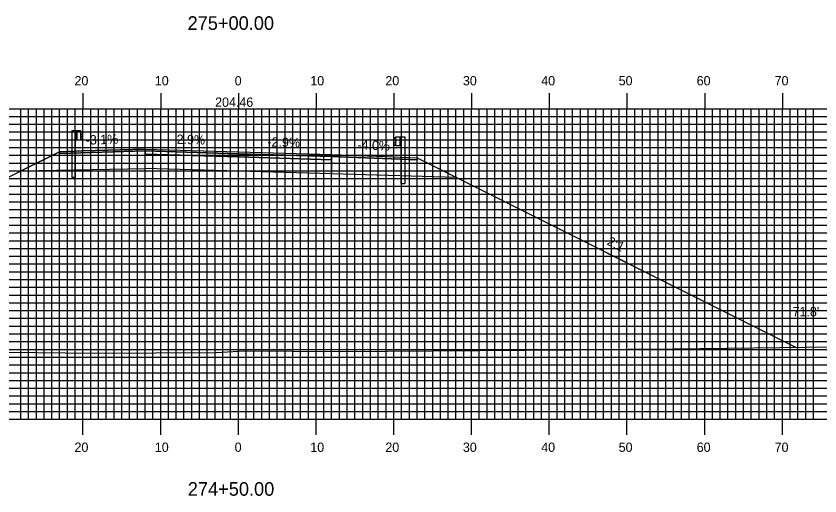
# Model space of a CAD drawing. Extents: x 1809406 to 1809749, y 442591 to 442811.
# Drawn here: x 1809543.2 to 1809646.7, y 442658.8 to 442720.6 of the extents above; entities that cross this region are included whole.
import ezdxf

# ---------------------------------------------------------------- set-up
doc = ezdxf.new("R2010")
doc.units = 0
for name, color, linetype in [('ANNOTATION', 7, 'Continuous'), ('D_Guardrail_Beam_Lt', 7, 'Continuous'), ('D_Guardrail_Beam_Rt', 7, 'Continuous'), ('D_Roadway_Centerline', 7, 'Continuous'), ('D_Roadway_Centerline_Text', 7, 'Continuous'), ('D_Roadway_Edge_Shoulder', 7, 'Continuous'), ('D_Roadway_Edge_TW', 7, 'Continuous'), ('D_Roadway_Pavement', 7, 'Continuous'), ('D_Roadway_SlopeLines', 7, 'Continuous'), ('D_Roadway_SubGrade', 7, 'Continuous'), ('D_Text_Standard', 7, 'Continuous'), ('H_V ANNOTATION', 7, 'Continuous'), ('MAJOR', 7, 'Continuous'), ('MINOR', 7, 'Continuous'), ('S_Roadway_Centerline', 7, 'Continuous')]:
    doc.layers.add(name, color=color, linetype=linetype)

msp = doc.modelspace()

# ---------------------------------------------------------------- linework, layer by layer
at = {"layer": 'D_Guardrail_Beam_Lt'}
for p, q in [((1809550.41, 442705.8), (1809550.41, 442699.8)), ((1809550.88, 442705.8), (1809550.41, 442705.8)), ((1809551.57, 442705.8), (1809550.88, 442705.8)), ((1809550.88, 442705.8), (1809550.88, 442704.64)), ((1809550.94, 442705.8), (1809550.94, 442704.64)), ((1809551.05, 442705.8), (1809551.05, 442704.64)), ((1809551.57, 442704.64), (1809551.57, 442705.8)), ((1809551.57, 442705.72), (1809551.64, 442705.71)), ((1809551.57, 442705.26), (1809551.57, 442705.19)), ((1809551.8, 442705.46), (1809551.6, 442705.32)), ((1809551.66, 442705.7), (1809551.8, 442705.6)), ((1809550.88, 442704.64), (1809551.57, 442704.64)), ((1809550.9, 442699.8), (1809550.9, 442704.64)), ((1809551.64, 442704.74), (1809551.57, 442704.72)), ((1809551.6, 442705.12), (1809551.8, 442704.99)), ((1809551.8, 442704.84), (1809551.66, 442704.74)), ((1809550.9, 442699.8), (1809550.41, 442699.8))]:
    msp.add_line(p, q, dxfattribs=at)
for centre, major_axis, start_param, end_param in [((1809551.65, 442705.26), (-0.0789, 0), 5.323254, 6.283185), ((1809551.65, 442705.19), (-0.0789, 0), 6.283185, 7.243116), ((1809551.63, 442705.67), (0.0417, 0), 0.959931, 1.376053), ((1809551.75, 442705.53), (0.0877, 0), 5.323254, 7.243116), ((1809551.63, 442704.78), (0.0417, 0), 4.907132, 5.323254), ((1809551.75, 442704.91), (0.0877, 0), 5.323254, 7.243116)]:
    msp.add_ellipse(centre, major_axis=major_axis, ratio=0.995501, start_param=start_param, end_param=end_param, dxfattribs=at)
at = {"layer": 'D_Guardrail_Beam_Rt'}
for p, q in [((1809592.02, 442704.93), (1809591.87, 442704.83)), ((1809591.87, 442704.69), (1809592.07, 442704.55)), ((1809592.07, 442704.35), (1809591.87, 442704.22)), ((1809592.11, 442704.95), (1809592.03, 442704.94)), ((1809592.1, 442704.49), (1809592.1, 442704.42)), ((1809592.11, 442705.03), (1809592.8, 442705.03)), ((1809592.11, 442703.87), (1809592.11, 442705.03)), ((1809592.63, 442705.03), (1809592.63, 442703.87)), ((1809592.73, 442705.03), (1809592.73, 442703.87)), ((1809592.8, 442705.03), (1809593.27, 442705.03)), ((1809592.8, 442705.03), (1809592.8, 442703.87)), ((1809593.27, 442705.03), (1809593.27, 442699.03)), ((1809591.87, 442704.07), (1809592.02, 442703.97)), ((1809592.03, 442703.97), (1809592.11, 442703.95)), ((1809592.8, 442703.87), (1809592.11, 442703.87)), ((1809592.77, 442699.03), (1809592.77, 442703.87)), ((1809592.77, 442699.03), (1809593.27, 442699.03))]:
    msp.add_line(p, q, dxfattribs=at)
for centre, major_axis, start_param, end_param in [((1809591.93, 442704.76), (-0.0877, 0), 5.323254, 7.243116), ((1809591.93, 442704.14), (-0.0877, 0), 5.323254, 7.243116), ((1809592.04, 442704.9), (-0.0417, 0), 4.907132, 5.323254), ((1809592.02, 442704.49), (0.0789, 0), 0, 0.959931), ((1809592.02, 442704.42), (0.0789, 0), 5.323254, 6.283185), ((1809592.04, 442704.01), (-0.0417, 0), 0.959931, 1.376053)]:
    msp.add_ellipse(centre, major_axis=major_axis, ratio=0.995501, start_param=start_param, end_param=end_param, dxfattribs=at)
at = {"layer": 'D_Roadway_Centerline'}
msp.add_lwpolyline([(1809495.74, 442676.58), (1809543.88, 442700.65), (1809548.84, 442703.13), (1809551.84, 442703.22), (1809559.84, 442703.47), (1809571.84, 442703.12), (1809583.84, 442702.77), (1809591.84, 442702.45), (1809594.84, 442702.33), (1809599.89, 442699.8), (1809643.63, 442677.93)], dxfattribs=at)
at = {"layer": 'D_Roadway_Edge_Shoulder'}
for points in [[(1809559.84, 442703.47), (1809551.84, 442703.22), (1809551.84, 442703.22), (1809548.84, 442703.13), (1809548.84, 442702.88), (1809559.84, 442703.22)], [(1809583.84, 442702.77), (1809591.84, 442702.45), (1809591.84, 442702.45), (1809594.84, 442702.33), (1809594.84, 442702.08), (1809583.84, 442702.52)]]:
    msp.add_lwpolyline(points, close=True, dxfattribs=at)
at = {"layer": 'D_Roadway_Edge_TW'}
msp.add_lwpolyline([(1809559.84, 442703.22), (1809559.84, 442703.47), (1809571.84, 442703.12), (1809583.84, 442702.77), (1809583.84, 442702.52), (1809571.84, 442702.87)], close=True, dxfattribs=at)
at = {"layer": 'D_Roadway_Pavement'}
msp.add_lwpolyline([(1809559.84, 442702.8), (1809559.84, 442703.22), (1809571.84, 442702.87), (1809583.84, 442702.52), (1809583.84, 442702.1), (1809571.84, 442702.45)], close=True, dxfattribs=at)
for points in [[(1809559.84, 442703.22), (1809559.84, 442702.8)], [(1809583.84, 442702.52), (1809583.84, 442702.1)]]:
    msp.add_lwpolyline(points, dxfattribs=at)
at = {"layer": 'D_Roadway_SlopeLines'}
for points in [[(1809548.84, 442703.13), (1809495.74, 442676.58)], [(1809594.84, 442702.33), (1809643.63, 442677.93)]]:
    msp.add_lwpolyline(points, dxfattribs=at)
at = {"layer": 'D_Roadway_SubGrade'}
for points in [[(1809559.84, 442702.8), (1809559.84, 442703.22), (1809548.84, 442702.88), (1809548.84, 442703.13), (1809543.88, 442700.65), (1809559.84, 442700.97)], [(1809559.84, 442700.97), (1809559.84, 442703.22), (1809559.84, 442702.8), (1809571.84, 442702.45), (1809583.84, 442702.1), (1809583.84, 442702.52), (1809583.84, 442700.27), (1809571.84, 442700.62)], [(1809583.84, 442702.1), (1809583.84, 442702.52), (1809594.84, 442702.08), (1809594.84, 442702.33), (1809599.89, 442699.8), (1809583.84, 442700.27)]]:
    msp.add_lwpolyline(points, close=True, dxfattribs=at)
at = {"layer": 'MAJOR'}
for p, q in [((1809551.84, 442710.67), (1809551.84, 442708.67)), ((1809561.84, 442710.67), (1809561.84, 442708.67)), ((1809571.84, 442710.67), (1809571.84, 442708.67)), ((1809581.84, 442710.67), (1809581.84, 442708.67)), ((1809591.84, 442710.67), (1809591.84, 442708.67)), ((1809601.84, 442710.67), (1809601.84, 442708.67)), ((1809611.84, 442710.67), (1809611.84, 442708.67)), ((1809621.84, 442710.67), (1809621.84, 442708.67)), ((1809631.84, 442710.67), (1809631.84, 442708.67)), ((1809641.84, 442710.67), (1809641.84, 442708.67)), ((1809431.84, 442708.67), (1809711.84, 442708.67)), ((1809431.84, 442708.67), (1809711.84, 442708.67)), ((1809551.84, 442668.67), (1809551.84, 442708.67)), ((1809561.84, 442668.67), (1809561.84, 442708.67)), ((1809571.84, 442668.67), (1809571.84, 442708.67)), ((1809581.84, 442668.67), (1809581.84, 442708.67)), ((1809591.84, 442668.67), (1809591.84, 442708.67)), ((1809601.84, 442668.67), (1809601.84, 442708.67)), ((1809611.84, 442668.67), (1809611.84, 442708.67)), ((1809621.84, 442668.67), (1809621.84, 442708.67)), ((1809631.84, 442668.67), (1809631.84, 442708.67)), ((1809641.84, 442668.67), (1809641.84, 442708.67)), ((1809431.84, 442703.67), (1809711.84, 442703.67)), ((1809431.84, 442698.67), (1809711.84, 442698.67)), ((1809431.84, 442693.67), (1809711.84, 442693.67)), ((1809431.84, 442688.67), (1809711.84, 442688.67)), ((1809431.84, 442683.67), (1809711.84, 442683.67)), ((1809431.84, 442678.67), (1809711.84, 442678.67)), ((1809431.84, 442673.67), (1809711.84, 442673.67)), ((1809431.84, 442668.67), (1809711.84, 442668.67)), ((1809431.84, 442668.67), (1809711.84, 442668.67)), ((1809551.84, 442666.66), (1809551.84, 442668.67)), ((1809561.84, 442666.66), (1809561.84, 442668.67)), ((1809571.84, 442666.66), (1809571.84, 442668.67)), ((1809581.84, 442666.66), (1809581.84, 442668.67)), ((1809591.84, 442666.66), (1809591.84, 442668.67)), ((1809601.84, 442666.66), (1809601.84, 442668.67)), ((1809611.84, 442666.66), (1809611.84, 442668.67)), ((1809621.84, 442666.66), (1809621.84, 442668.67)), ((1809631.84, 442666.66), (1809631.84, 442668.67)), ((1809641.84, 442666.66), (1809641.84, 442668.67))]:
    msp.add_line(p, q, dxfattribs=at)
at = {"layer": 'MINOR'}
for p, q in [((1809543.84, 442668.67), (1809543.84, 442708.67)), ((1809544.84, 442668.67), (1809544.84, 442708.67)), ((1809545.84, 442668.67), (1809545.84, 442708.67)), ((1809546.84, 442668.67), (1809546.84, 442708.67)), ((1809547.84, 442668.67), (1809547.84, 442708.67)), ((1809548.84, 442668.67), (1809548.84, 442708.67)), ((1809549.84, 442668.67), (1809549.84, 442708.67)), ((1809550.84, 442668.67), (1809550.84, 442708.67)), ((1809552.84, 442668.67), (1809552.84, 442708.67)), ((1809553.84, 442668.67), (1809553.84, 442708.67)), ((1809554.84, 442668.67), (1809554.84, 442708.67)), ((1809555.84, 442668.67), (1809555.84, 442708.67)), ((1809556.84, 442668.67), (1809556.84, 442708.67)), ((1809557.84, 442668.67), (1809557.84, 442708.67)), ((1809558.84, 442668.67), (1809558.84, 442708.67)), ((1809559.84, 442668.67), (1809559.84, 442708.67)), ((1809560.84, 442668.67), (1809560.84, 442708.67)), ((1809562.84, 442668.67), (1809562.84, 442708.67)), ((1809563.84, 442668.67), (1809563.84, 442708.67)), ((1809564.84, 442668.67), (1809564.84, 442708.67)), ((1809565.84, 442668.67), (1809565.84, 442708.67)), ((1809566.84, 442668.67), (1809566.84, 442708.67)), ((1809567.84, 442668.67), (1809567.84, 442708.67)), ((1809568.84, 442668.67), (1809568.84, 442708.67)), ((1809569.84, 442668.67), (1809569.84, 442708.67)), ((1809570.84, 442668.67), (1809570.84, 442708.67)), ((1809572.84, 442668.67), (1809572.84, 442708.67)), ((1809573.84, 442668.67), (1809573.84, 442708.67)), ((1809574.84, 442668.67), (1809574.84, 442708.67)), ((1809575.84, 442668.67), (1809575.84, 442708.67)), ((1809576.84, 442668.67), (1809576.84, 442708.67)), ((1809577.84, 442668.67), (1809577.84, 442708.67)), ((1809578.84, 442668.67), (1809578.84, 442708.67)), ((1809579.84, 442668.67), (1809579.84, 442708.67)), ((1809580.84, 442668.67), (1809580.84, 442708.67)), ((1809582.84, 442668.67), (1809582.84, 442708.67)), ((1809583.84, 442668.67), (1809583.84, 442708.67)), ((1809584.84, 442668.67), (1809584.84, 442708.67)), ((1809585.84, 442668.67), (1809585.84, 442708.67)), ((1809586.84, 442668.67), (1809586.84, 442708.67)), ((1809587.84, 442668.67), (1809587.84, 442708.67)), ((1809588.84, 442668.67), (1809588.84, 442708.67)), ((1809589.84, 442668.67), (1809589.84, 442708.67)), ((1809590.84, 442668.67), (1809590.84, 442708.67)), ((1809592.84, 442668.67), (1809592.84, 442708.67)), ((1809593.84, 442668.67), (1809593.84, 442708.67)), ((1809594.84, 442668.67), (1809594.84, 442708.67)), ((1809595.84, 442668.67), (1809595.84, 442708.67)), ((1809596.84, 442668.67), (1809596.84, 442708.67)), ((1809597.84, 442668.67), (1809597.84, 442708.67)), ((1809598.84, 442668.67), (1809598.84, 442708.67)), ((1809599.84, 442668.67), (1809599.84, 442708.67)), ((1809600.84, 442668.67), (1809600.84, 442708.67)), ((1809602.84, 442668.67), (1809602.84, 442708.67)), ((1809603.84, 442668.67), (1809603.84, 442708.67)), ((1809604.84, 442668.67), (1809604.84, 442708.67)), ((1809605.84, 442668.67), (1809605.84, 442708.67)), ((1809606.84, 442668.67), (1809606.84, 442708.67)), ((1809607.84, 442668.67), (1809607.84, 442708.67)), ((1809608.84, 442668.67), (1809608.84, 442708.67)), ((1809609.84, 442668.67), (1809609.84, 442708.67)), ((1809610.84, 442668.67), (1809610.84, 442708.67)), ((1809612.84, 442668.67), (1809612.84, 442708.67)), ((1809613.84, 442668.67), (1809613.84, 442708.67)), ((1809614.84, 442668.67), (1809614.84, 442708.67)), ((1809615.84, 442668.67), (1809615.84, 442708.67)), ((1809616.84, 442668.67), (1809616.84, 442708.67)), ((1809617.84, 442668.67), (1809617.84, 442708.67)), ((1809618.84, 442668.67), (1809618.84, 442708.67)), ((1809619.84, 442668.67), (1809619.84, 442708.67)), ((1809620.84, 442668.67), (1809620.84, 442708.67)), ((1809622.84, 442668.67), (1809622.84, 442708.67)), ((1809623.84, 442668.67), (1809623.84, 442708.67)), ((1809624.84, 442668.67), (1809624.84, 442708.67)), ((1809625.84, 442668.67), (1809625.84, 442708.67)), ((1809626.84, 442668.67), (1809626.84, 442708.67)), ((1809627.84, 442668.67), (1809627.84, 442708.67)), ((1809628.84, 442668.67), (1809628.84, 442708.67)), ((1809629.84, 442668.67), (1809629.84, 442708.67)), ((1809630.84, 442668.67), (1809630.84, 442708.67)), ((1809632.84, 442668.67), (1809632.84, 442708.67)), ((1809633.84, 442668.67), (1809633.84, 442708.67)), ((1809634.84, 442668.67), (1809634.84, 442708.67)), ((1809635.84, 442668.67), (1809635.84, 442708.67)), ((1809636.84, 442668.67), (1809636.84, 442708.67)), ((1809637.84, 442668.67), (1809637.84, 442708.67)), ((1809638.84, 442668.67), (1809638.84, 442708.67)), ((1809639.84, 442668.67), (1809639.84, 442708.67)), ((1809640.84, 442668.67), (1809640.84, 442708.67)), ((1809642.84, 442668.67), (1809642.84, 442708.67)), ((1809643.84, 442668.67), (1809643.84, 442708.67)), ((1809644.84, 442668.67), (1809644.84, 442708.67)), ((1809645.84, 442668.67), (1809645.84, 442708.67)), ((1809431.84, 442707.67), (1809711.84, 442707.67)), ((1809431.84, 442706.67), (1809711.84, 442706.67)), ((1809431.84, 442705.67), (1809711.84, 442705.67)), ((1809431.84, 442704.67), (1809711.84, 442704.67)), ((1809431.84, 442702.67), (1809711.84, 442702.67)), ((1809431.84, 442701.67), (1809711.84, 442701.67)), ((1809431.84, 442700.67), (1809711.84, 442700.67)), ((1809431.84, 442699.67), (1809711.84, 442699.67)), ((1809431.84, 442697.67), (1809711.84, 442697.67)), ((1809431.84, 442696.67), (1809711.84, 442696.67)), ((1809431.84, 442695.67), (1809711.84, 442695.67)), ((1809431.84, 442694.67), (1809711.84, 442694.67)), ((1809431.84, 442692.67), (1809711.84, 442692.67)), ((1809431.84, 442691.67), (1809711.84, 442691.67)), ((1809431.84, 442690.67), (1809711.84, 442690.67)), ((1809431.84, 442689.67), (1809711.84, 442689.67)), ((1809431.84, 442687.67), (1809711.84, 442687.67)), ((1809431.84, 442686.67), (1809711.84, 442686.67)), ((1809431.84, 442685.67), (1809711.84, 442685.67)), ((1809431.84, 442684.67), (1809711.84, 442684.67)), ((1809431.84, 442682.67), (1809711.84, 442682.67)), ((1809431.84, 442681.67), (1809711.84, 442681.67)), ((1809431.84, 442680.67), (1809711.84, 442680.67)), ((1809431.84, 442679.67), (1809711.84, 442679.67)), ((1809431.84, 442677.67), (1809711.84, 442677.67)), ((1809431.84, 442676.67), (1809711.84, 442676.67)), ((1809431.84, 442675.67), (1809711.84, 442675.67)), ((1809431.84, 442674.67), (1809711.84, 442674.67)), ((1809431.84, 442672.67), (1809711.84, 442672.67)), ((1809431.84, 442671.67), (1809711.84, 442671.67)), ((1809431.84, 442670.67), (1809711.84, 442670.67)), ((1809431.84, 442669.67), (1809711.84, 442669.67))]:
    msp.add_line(p, q, dxfattribs=at)
at = {"layer": 'S_Roadway_Centerline'}
msp.add_lwpolyline([(1809538.25, 442677.36), (1809553.38, 442677.19), (1809568.97, 442677.27), (1809572.62, 442677.47), (1809585.01, 442677.4), (1809620.74, 442677.67), (1809622.01, 442677.68), (1809622.58, 442677.69), (1809624.52, 442677.7), (1809672.05, 442678.29), (1809680.89, 442678.33), (1809700.54, 442678.23), (1809711.84, 442678.21)], dxfattribs=at)

# ---------------------------------------------------------------- texts
at = {"layer": 'ANNOTATION'}
for s, rotation, p in [('-3.1%', 1.772, (1809552.21, 442704.03)), ('2.9%', 358.3354, (1809563.88, 442704.15)), ('-2.9%', 358.3354, (1809575.56, 442703.81)), ('-4.0%', 357.7094, (1809587.13, 442703.44)), ('2:1', 333.4349, (1809619.17, 442691.2))]:
    msp.add_text(s, height=1.2, rotation=rotation, dxfattribs=at).set_placement(p)
at = {"layer": 'D_Roadway_Centerline'}
for s, p in [('C', (1809571.83, 442703.12)), ('L', (1809571.84, 442703.11))]:
    msp.add_text(s, height=0.0146, dxfattribs=at).set_placement(p)
at = {"layer": 'D_Roadway_Centerline_Text'}
msp.add_text('204.46', height=1.2, dxfattribs=at).set_placement((1809568.84, 442708.91))
at = {"layer": 'D_Text_Standard'}
msp.add_text("71.8'", height=1.2, dxfattribs=at).set_placement((1809643.15, 442681.93))
at = {"layer": 'H_V ANNOTATION'}
for s, height, p in [('275+00.00', 1.75, (1809565.3, 442718.82)), ('20', 1.2, (1809550.75, 442711.67)), ('10', 1.2, (1809561.09, 442711.67)), ('0', 1.2, (1809571.36, 442711.67)), ('10', 1.2, (1809581.09, 442711.67)), ('20', 1.2, (1809590.75, 442711.67)), ('30', 1.2, (1809600.73, 442711.67)), ('40', 1.2, (1809610.81, 442711.67)), ('50', 1.2, (1809620.77, 442711.67)), ('60', 1.2, (1809630.81, 442711.67)), ('70', 1.2, (1809640.84, 442711.67)), ('20', 1.2, (1809550.75, 442664.47)), ('10', 1.2, (1809561.09, 442664.47)), ('0', 1.2, (1809571.36, 442664.47)), ('10', 1.2, (1809581.09, 442664.47)), ('20', 1.2, (1809590.75, 442664.47)), ('30', 1.2, (1809600.73, 442664.47)), ('40', 1.2, (1809610.81, 442664.47)), ('50', 1.2, (1809620.77, 442664.47)), ('60', 1.2, (1809630.81, 442664.47)), ('70', 1.2, (1809640.84, 442664.47)), ('274+50.00', 1.75, (1809565.33, 442658.82))]:
    msp.add_text(s, height=height, dxfattribs=at).set_placement(p)

doc.saveas('drawing.dxf')
